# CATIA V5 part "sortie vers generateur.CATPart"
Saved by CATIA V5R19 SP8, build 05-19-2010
Part number: portesatellite 1
Bounding box of the stored display mesh (mm): x -43.564 to 66.75, y -29.25 to 29.25, z -140 to 10
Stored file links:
  G:\EU_thinkMotion\CFAO_2010\St2M_groupe2\St2M_groupe2\npeyre\npeyre\sortie vers generateur.CATPart
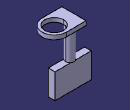
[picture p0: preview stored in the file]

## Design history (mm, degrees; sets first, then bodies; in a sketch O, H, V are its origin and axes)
Parameters
  `diamètre sortie vers generateur` = 10 mm
  `Diametre alesage satellite` = 45 mm
  `Distance axe-contact sortie/carter` = 90 mm
  `distance axe couvercle-axe pivot sortie` = 37.5 mm
Body1 (main body)
  Sketch1 on xy-plane, origin (0, 0, 0), H (1, 0, 0), V (0, 1, 0)
    circle A1 centre (0, 0) radius 10
    point P1 (0, 0)
    radius A1 = 10 {= `diamètre sortie vers generateur`}
    coincidence: P1 O
  Pad1: profile Sketch1, direction (0, 0, -1), length 80 {= 4*`détruit_Longueur satellite 1`}
  Sketch2 on end face of Pad1, origin (0, 0, -80), H (1, 0, 0), V (0, -1, 0)
    line L1 (43.5637, 8.076) -> (43.5637, -8.076)
    line L2 (43.5637, -8.076) -> (-43.5637, -8.076)
    line L3 (-43.5637, -8.076) -> (-43.5637, 8.076)
    line L4 (-43.5637, 8.076) -> (43.5637, 8.076)
    vertical: L1 V, L3 V
    horizontal: L2 H, L4 H
    equidistance: L1 L3 O, L2 L4 O
  Pad2: profile Sketch2, direction (0, 0, -1), length 60 {= `détruit_Longueur satellite 1` *3}
  Sketch3 on xy-plane, origin (0, 0, 0), H (1, 0, 0), V (0, 1, 0)
    circle A1 centre (37.5, 0) radius 22.5
    point P1 (37.5, 0)
    point P2 (-10, 29.25)
    line L1 (-10, 29.25) -> (-10, -29.25)
    line L2 (-10, -29.25) -> (37.5, -29.25)
    arc A2 centre (37.5, 0) radius 29.25 from (37.5, -29.25) to (37.5, 29.25) ccw
    point P5 (37.5, 0)
    line L3 (37.5, 29.25) -> (-10, 29.25)
    point P7 (-10, 29.25)
    reference projected circle E1 centre (0, 0) radius 10 from edge [face of Pad1 from Sketch1.A1 | start face of Pad1]
    axis line L4 (66.75, 18.0992) -> (66.75, -52.8821)
    radius A1 = 22.5 {= `Diametre alesage satellite` /2}
    radius A2 = 29.25 {= `Diametre alesage satellite`/2*1.3}
    distance O P5 = 37.5 {= `distance axe couvercle-axe pivot sortie`}
    coincidence: P1 H, P7 L1, P7 P2, P5 P1
    vertical: L1 V, L4 V
    horizontal: L2 H
    tangency: A2 L2, L3 A2, L1 E1, L4 A2
  Pad3: profile Sketch3, direction (0, 0, 1), length 10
